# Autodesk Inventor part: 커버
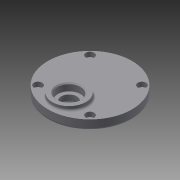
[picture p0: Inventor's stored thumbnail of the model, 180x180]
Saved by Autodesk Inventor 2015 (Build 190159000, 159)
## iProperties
Created: 2014-12
Part Number: 커버
Material: 일반
Document SubType Name: Modeling
Designer: LHJ
Density: 1 g/cm^3
Appearance: 기본값
Author: LHJ
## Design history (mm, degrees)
sketch "스케치1"
  geometry: C1 r 40 at (0, 0); 1 further point
  constraints: 1 centre point, 1 coincident
  dimensions: "d0" = 80 diameter of C1
extrude "돌출1" new body sketch "스케치1" distance "d1" = 9; taper "d2" = 0 deg
sketch "스케치2"
  geometry: C1 r 16 at (0, -20); 1 further point
  constraints: 1 centre point, 1 vertical alignment
  dimensions: "d3" = 32 diameter of C1; "d4" = 20 distance of C1.centre point (0, 0)
extrude "돌출2" join sketch "스케치2" distance "d5" = 4; taper "d6" = 0 deg
sketch "스케치3"
  geometry: C1 r 16 at (0, -20) reference; C2 r 40 at (0, 0) reference; C3 r 14 at (0, -20); C4 r 14 at (0, 11); 1 further point
  constraints: 2 centre point, 1 coincident, 1 vertical alignment
  dimensions: "d7" = 28 diameter of C3; "d8" = 28 diameter of C4; "d9" = 11 distance of C4.centre point (0, 0)
extrude "돌출3" join sketch "스케치3" distance "d10" = 3; taper "d11" = 0 deg
sketch "스케치4"
  geometry: C1 r 16 at (0, 0) reference; C2 r 11 at (0, 0); 1 further point
  constraints: 1 centre point, 1 coincident
  dimensions: "d12" = 22 diameter of C2
extrude "돌출4" cut sketch "스케치4" distance "d13" = 7; taper "d14" = 0 deg
sketch "스케치5"
  geometry: C1 r 7.5 at (0, 0); C2 r 11 at (0, 0) reference; 1 further point
  constraints: 1 centre point, 1 concentric
  dimensions: "d15" = 15 diameter of C1
extrude "돌출5" cut sketch "스케치5" distance "d16" = 2; taper "d17" = 0 deg
sketch "스케치6"
  geometry: C1 r 11 at (0, 0); C2 r 14 at (0, 0) reference; 1 further point
  constraints: 1 centre point, 1 concentric
  dimensions: "d18" = 22 diameter of C1
extrude "돌출6" cut sketch "스케치6" distance "d19" = 7; taper "d20" = 0 deg
sketch "스케치7"
  geometry: 1 further point
sketch "스케치8"
  geometry: C1 r 11 at (0, 0); C2 r 14 at (0, 0) reference; 1 further point
  constraints: 1 centre point, 1 concentric
  dimensions: "d21" = 22 diameter of C1
extrude "돌출7" cut sketch "스케치8" distance "d22" = 7; taper "d23" = 0 deg
sketch "스케치9"
  geometry: C1 r 9 at (0, 0); 2 further points
  constraints: 1 centre point, 1 vertical alignment, 1 other
  dimensions: "d24" = 18 diameter of C1
extrude "돌출8" cut sketch "스케치9" distance "d25" = 1; taper "d26" = 0 deg
sketch "스케치10" dims "d28" = 70
  geometry: L1 (0, 0)-(-24.749, 24.749); L2 (0, 0)-(-62.387, 0); 2 further points
  constraints: 4 end point, 2 coincident, 1 horizontal, 3 other
  dimensions: "d27" = 45 deg angle of L1 L2
hole "구멍1" sketch "스케치10" at (-24.749, 24.749) diameter "d29" = 4.5; stored, may be unused: countersink angle "d33" = 90 deg, drill point angle "d35" = 0 deg; dims "d30" = 6, "d31" = 8, "d32" = 4.4, "d34" = 8
fillet "모깎기1" dims "d39" = 2
fillet "모깎기2" dims "d40" = 0.3
chamfer "모따기1" distance "d41" = 1; stored, may be unused: second distance "d42" = 2, angle "d43" = 45 deg
chamfer "모따기2" distance "d44" = 1; stored, may be unused: second distance "d45" = 2, angle "d46" = 45 deg
node "솔리드1"
pattern_circular "원형 패턴1" dims angle "d37" = 360 deg
node "투영된 루프1"
node "절단 모서리 투영1"
